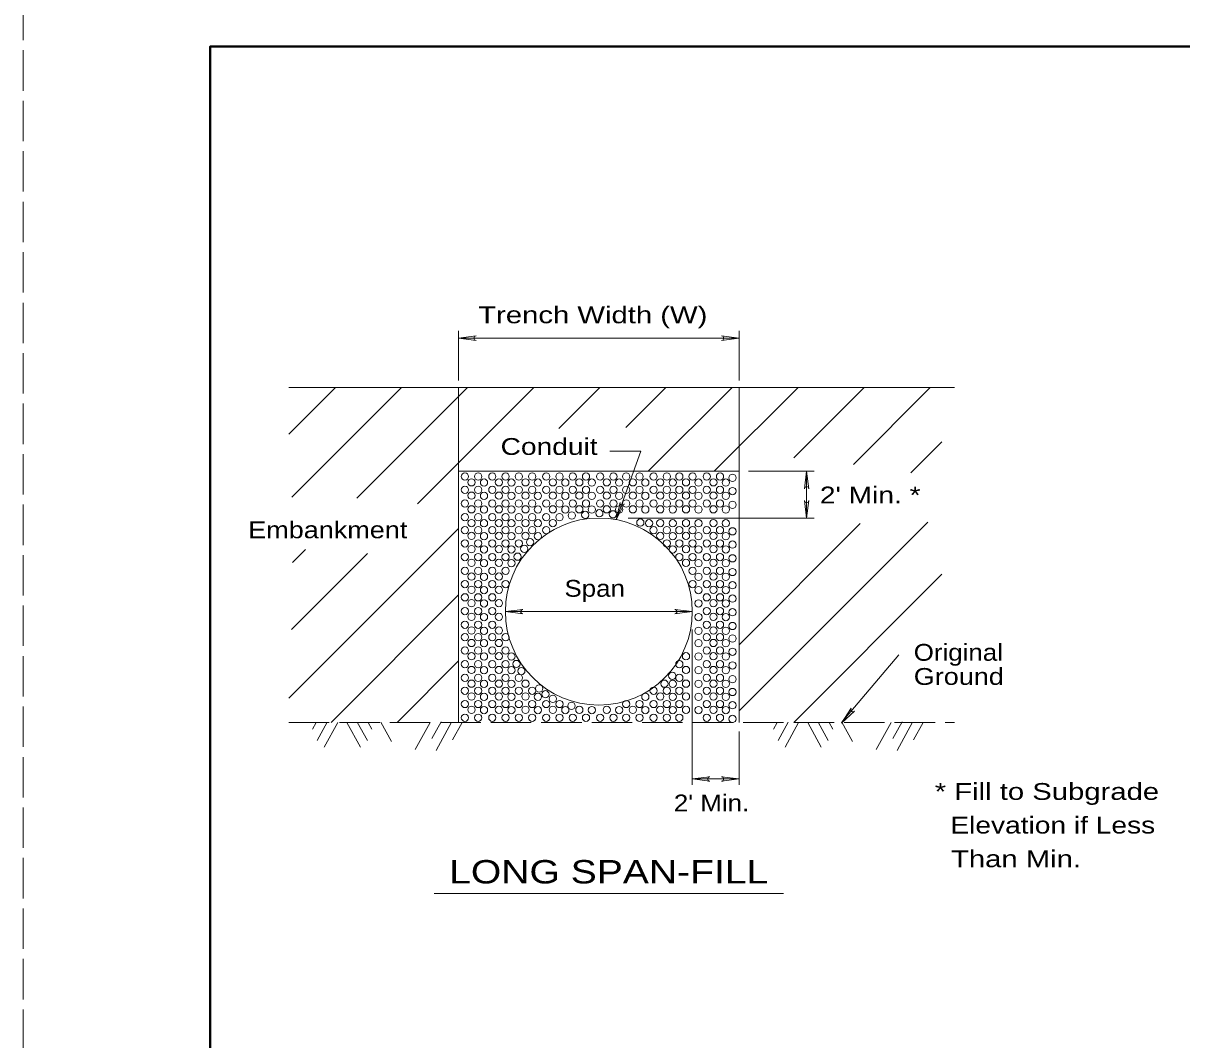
# Model space of a CAD drawing. Extents: x 750.7 to 784.7, y 834.8 to 878.8.
# Drawn here: x 750.65 to 763.05, y 845.66 to 856.53 of the extents above; entities that cross this region are included whole.
import ezdxf

# ---------------------------------------------------------------- set-up
doc = ezdxf.new("R2010")
doc.units = 0
doc.header["$LTSCALE"] = 0.072
doc.linetypes.add('LONG_DASHED', pattern=[7.5, 6, -1.5])
doc.layers.add('1', color=7, linetype='Continuous', lineweight=13)
doc.layers.add('47', color=7, linetype='Continuous', lineweight=13)

msp = doc.modelspace()

# ---------------------------------------------------------------- linework, layer by layer
at = {"layer": '1', "lineweight": 40}
msp.add_line((752.65083, 856.28433), (784.15083, 856.28433), dxfattribs=at)
at = {"layer": '1'}
for p, q in [((755.30908, 852.71117), (755.30908, 853.24292)), ((755.30908, 853.16492), (758.30908, 853.16492)), ((758.30908, 852.71117), (758.30908, 853.24292)), ((753.49175, 852.13867), (753.99142, 852.63842)), ((753.49367, 852.63842), (760.613, 852.63842)), ((753.52558, 851.46542), (754.6985, 852.63842)), ((754.22158, 851.45425), (755.40558, 852.63842)), ((754.86808, 851.39367), (756.11267, 852.63842)), ((755.30908, 852.63842), (755.30908, 849.05517)), ((756.3795, 852.19808), (756.81975, 852.63842)), ((757.097, 852.2085), (757.52683, 852.63842)), ((757.33717, 851.74158), (758.23392, 852.63842)), ((758.04417, 851.74158), (758.94092, 852.63842)), ((758.30908, 852.63842), (758.30908, 849.05517)), ((758.89425, 851.88467), (759.648, 852.63842)), ((759.53183, 851.81508), (760.35508, 852.63842)), ((760.148, 851.72417), (760.48017, 852.05642)), ((755.30908, 851.74158), (758.30908, 851.74158)), ((758.41008, 851.74158), (759.11142, 851.74158)), ((759.0315, 851.24025), (759.0315, 851.74158)), ((757.123, 851.24025), (759.11142, 851.24025)), ((758.30908, 849.17792), (760.32758, 851.19667)), ((758.30908, 849.88508), (759.60642, 851.18258)), ((753.49408, 849.31242), (755.30908, 851.12758)), ((753.52233, 850.04783), (754.33533, 850.86092)), ((753.53283, 850.7655), (753.67117, 850.90383)), ((758.8935, 849.05517), (760.477, 850.63883)), ((753.94392, 849.05517), (755.30908, 850.4205)), ((755.80908, 850.2405), (757.80908, 850.2405)), ((757.80908, 850.04683), (757.80908, 848.38733)), ((754.651, 849.05517), (755.30908, 849.71325)), ((759.40575, 849.05517), (760.01683, 849.77708)), ((755.12275, 849.0605), (755.02433, 848.88208)), ((760.053, 849.0605), (759.95458, 848.88208)), ((753.78683, 849.05517), (753.7475, 848.98383)), ((753.90342, 849.05658), (753.79558, 848.86108)), ((754.0155, 849.05267), (753.87058, 848.79008)), ((754.11342, 849.05267), (754.25833, 848.79008)), ((754.2255, 849.05658), (754.33333, 848.86108)), ((754.34208, 849.05517), (754.38142, 848.98383)), ((754.47842, 849.05567), (754.591, 848.85158)), ((755.00558, 849.05517), (754.845, 848.76417)), ((755.23475, 849.05658), (755.06858, 848.75542)), ((755.34683, 849.05267), (755.24508, 848.86825)), ((758.30908, 848.95567), (758.30908, 848.38733)), ((758.71708, 849.05517), (758.67775, 848.98383)), ((758.83367, 849.05658), (758.72583, 848.86108)), ((758.94575, 849.05267), (758.80083, 848.79008)), ((759.04367, 849.05267), (759.18858, 848.79008)), ((759.15575, 849.05658), (759.26358, 848.86108)), ((759.27233, 849.05517), (759.31167, 848.98383)), ((759.40867, 849.05567), (759.52125, 848.85158)), ((759.93583, 849.05517), (759.77525, 848.76417)), ((760.165, 849.05658), (759.99883, 848.75542)), ((760.27708, 849.05267), (760.17533, 848.86825)), ((757.80908, 848.4495), (758.30908, 848.4495)), ((755.04842, 847.22583), (758.78292, 847.22583))]:
    msp.add_line(p, q, dxfattribs=at)
at = {"layer": '1', "linetype": 'LONG_DASHED'}
msp.add_line((753.49367, 849.05517), (760.613, 849.05517), dxfattribs=at)
msp.add_lwpolyline([(750.65083, 834.78433), (784.65083, 834.78433), (784.65083, 856.78433), (750.65083, 856.78433)], close=True, dxfattribs=at)
at = {"layer": '1', "lineweight": 40}
for points in [[(784.15083, 835.28433), (752.65083, 835.28433), (752.65083, 856.28433), (784.15083, 856.28433)], [(784.15083, 835.28433), (752.65083, 835.28433), (752.65083, 856.28433)]]:
    msp.add_lwpolyline(points, dxfattribs=at)
at = {"layer": '1'}
msp.add_lwpolyline([(756.9255, 851.956), (757.26017, 851.956), (756.99517, 851.223)], dxfattribs=at)
for centre, radius in [((755.37663, 851.68461), 0.03892), ((755.44766, 851.62247), 0.03892), ((755.51866, 851.68464), 0.03892), ((755.66955, 851.68461), 0.03892), ((755.74058, 851.62247), 0.03892), ((755.81158, 851.68464), 0.03892), ((755.95363, 851.68461), 0.03892), ((756.02466, 851.62247), 0.03892), ((756.09566, 851.68464), 0.03892), ((756.24655, 851.68461), 0.03892), ((756.31758, 851.62247), 0.03892), ((756.38858, 851.68464), 0.03892), ((756.52963, 851.68461), 0.03892), ((756.60066, 851.62247), 0.03892), ((756.67166, 851.68464), 0.03892), ((756.82255, 851.68461), 0.03892), ((756.89358, 851.62247), 0.03892), ((756.96458, 851.68464), 0.03892), ((757.10221, 851.68461), 0.03892), ((757.17324, 851.62247), 0.03892), ((757.24424, 851.68464), 0.03892), ((757.39513, 851.68461), 0.03892), ((757.46616, 851.62247), 0.03892), ((757.53716, 851.68464), 0.03892), ((757.67038, 851.68461), 0.03892), ((757.74141, 851.62247), 0.03892), ((757.81241, 851.68464), 0.03892), ((757.9633, 851.68461), 0.03892), ((758.03433, 851.62247), 0.03892), ((758.10533, 851.68464), 0.03892), ((758.23849, 851.67131), 0.03892), ((755.37663, 851.54253), 0.03892), ((755.51866, 851.54256), 0.03892), ((755.58083, 851.62014), 0.03892), ((755.66955, 851.54253), 0.03892), ((755.81158, 851.54256), 0.03892), ((755.87374, 851.62014), 0.03892), ((755.95363, 851.54253), 0.03892), ((756.09566, 851.54256), 0.03892), ((756.15783, 851.62014), 0.03892), ((756.24655, 851.54253), 0.03892), ((756.38858, 851.54256), 0.03892), ((756.45074, 851.62014), 0.03892), ((756.52963, 851.54253), 0.03892), ((756.67166, 851.54256), 0.03892), ((756.73383, 851.62014), 0.03892), ((756.82255, 851.54253), 0.03892), ((756.96458, 851.54256), 0.03892), ((757.02674, 851.62014), 0.03892), ((757.10221, 851.54253), 0.03892), ((757.24424, 851.54256), 0.03892), ((757.30641, 851.62014), 0.03892), ((757.39513, 851.54253), 0.03892), ((757.53716, 851.54256), 0.03892), ((757.59933, 851.62014), 0.03892), ((757.67038, 851.54253), 0.03892), ((757.81241, 851.54256), 0.03892), ((757.87458, 851.62014), 0.03892), ((757.9633, 851.54253), 0.03892), ((758.10533, 851.54256), 0.03892), ((758.16749, 851.62014), 0.03892), ((758.23849, 851.52922), 0.03892), ((755.37663, 851.39603), 0.03892), ((755.44766, 851.48039), 0.03892), ((755.51866, 851.39606), 0.03892), ((755.58083, 851.47806), 0.03892), ((755.66955, 851.39603), 0.03892), ((755.74058, 851.48039), 0.03892), ((755.81158, 851.39606), 0.03892), ((755.87374, 851.47806), 0.03892), ((755.95363, 851.39603), 0.03892), ((756.02466, 851.48039), 0.03892), ((756.09566, 851.39606), 0.03892), ((756.15783, 851.47806), 0.03892), ((756.24655, 851.39603), 0.03892), ((756.31758, 851.48039), 0.03892), ((756.38858, 851.39606), 0.03892), ((756.45074, 851.47806), 0.03892), ((756.52963, 851.39603), 0.03892), ((756.60066, 851.48039), 0.03892), ((756.67166, 851.39606), 0.03892), ((756.73383, 851.47806), 0.03892), ((756.82255, 851.39603), 0.03892), ((756.89358, 851.48039), 0.03892), ((756.96458, 851.39606), 0.03892), ((757.02674, 851.47806), 0.03892), ((757.10221, 851.39603), 0.03892), ((757.17324, 851.48039), 0.03892), ((757.24424, 851.39606), 0.03892), ((757.30641, 851.47806), 0.03892), ((757.39513, 851.39603), 0.03892), ((757.46616, 851.48039), 0.03892), ((757.53716, 851.39606), 0.03892), ((757.59933, 851.47806), 0.03892), ((757.67038, 851.39603), 0.03892), ((757.74141, 851.48039), 0.03892), ((757.81241, 851.39606), 0.03892), ((757.87458, 851.47806), 0.03892), ((757.9633, 851.39603), 0.03892), ((758.03433, 851.48039), 0.03892), ((758.10533, 851.39606), 0.03892), ((758.16749, 851.47806), 0.03892), ((758.23849, 851.38272), 0.03892), ((755.44766, 851.33389), 0.03892), ((755.58083, 851.33156), 0.03892), ((755.74058, 851.33389), 0.03892), ((755.87374, 851.33156), 0.03892), ((756.02466, 851.33389), 0.03892), ((756.15783, 851.33156), 0.03892), ((756.31758, 851.33389), 0.03892), ((756.45074, 851.33156), 0.03892), ((756.52073, 851.26725), 0.03892), ((756.60066, 851.33389), 0.03892), ((756.66383, 851.27379), 0.03892), ((756.73383, 851.33156), 0.03892), ((756.81467, 851.29154), 0.03892), ((756.89358, 851.33389), 0.03892), ((756.96015, 851.28053), 0.03892), ((757.02674, 851.33156), 0.03892), ((757.17324, 851.33389), 0.03892), ((757.30641, 851.33156), 0.03892), ((757.46616, 851.33389), 0.03892), ((757.59933, 851.33156), 0.03892), ((757.74141, 851.33389), 0.03892), ((757.87458, 851.33156), 0.03892), ((758.03433, 851.33389), 0.03892), ((758.16749, 851.33156), 0.03892), ((755.37663, 851.24944), 0.03892), ((755.44766, 851.18731), 0.03892), ((755.51866, 851.24947), 0.03892), ((755.58083, 851.18497), 0.03892), ((755.66955, 851.24944), 0.03892), ((755.74058, 851.18731), 0.03892), ((755.81158, 851.24947), 0.03892), ((756.80908, 850.2405), 1), ((755.87374, 851.18497), 0.03892), ((755.95363, 851.24944), 0.03892), ((756.02466, 851.18731), 0.03892), ((756.09566, 851.24947), 0.03892), ((756.15783, 851.18497), 0.03892), ((756.24655, 851.24944), 0.03892), ((756.31758, 851.18731), 0.03892), ((756.38858, 851.24947), 0.03892), ((757.25314, 851.1917), 0.03892), ((757.34634, 851.18495), 0.03892), ((757.46616, 851.18731), 0.03892), ((757.59933, 851.18497), 0.03892), ((757.74141, 851.18731), 0.03892), ((757.87458, 851.18497), 0.03892), ((758.03433, 851.18731), 0.03892), ((758.16749, 851.18497), 0.03892), ((755.37663, 851.11178), 0.03892), ((755.44766, 851.04964), 0.03892), ((755.51866, 851.11181), 0.03892), ((755.58083, 851.04731), 0.03892), ((755.66955, 851.11178), 0.03892), ((755.74058, 851.04964), 0.03892), ((755.81158, 851.11181), 0.03892), ((755.87374, 851.04731), 0.03892), ((755.95363, 851.11178), 0.03892), ((756.02466, 851.04964), 0.03892), ((756.09566, 851.11181), 0.03892), ((756.15783, 851.04731), 0.03892), ((756.24655, 851.11178), 0.03892), ((757.39513, 851.11178), 0.03892), ((757.46616, 851.04964), 0.03892), ((757.53716, 851.11181), 0.03892), ((757.59933, 851.04731), 0.03892), ((757.67038, 851.11178), 0.03892), ((757.74141, 851.04964), 0.03892), ((757.81241, 851.11181), 0.03892), ((757.87458, 851.04731), 0.03892), ((757.9633, 851.11178), 0.03892), ((758.03433, 851.04964), 0.03892), ((758.10533, 851.11181), 0.03892), ((758.16749, 851.04731), 0.03892), ((758.23849, 851.09847), 0.03892), ((755.37663, 850.96969), 0.03892), ((755.44766, 850.90756), 0.03892), ((755.51866, 850.96972), 0.03892), ((755.58083, 850.90522), 0.03892), ((755.66955, 850.96969), 0.03892), ((755.74058, 850.90756), 0.03892), ((755.81158, 850.96972), 0.03892), ((755.87374, 850.90522), 0.03892), ((755.95363, 850.96969), 0.03892), ((756.01133, 850.91202), 0.03892), ((756.07342, 850.98305), 0.03892), ((757.53716, 850.96972), 0.03892), ((757.59933, 850.90522), 0.03892), ((757.67038, 850.96969), 0.03892), ((757.74141, 850.90756), 0.03892), ((757.81241, 850.96972), 0.03892), ((757.87458, 850.90522), 0.03892), ((757.9633, 850.96969), 0.03892), ((758.03433, 850.90756), 0.03892), ((758.10533, 850.96972), 0.03892), ((758.16749, 850.90522), 0.03892), ((758.23849, 850.95639), 0.03892), ((755.37663, 850.82319), 0.03892), ((755.44766, 850.76106), 0.03892), ((755.51866, 850.82322), 0.03892), ((755.58083, 850.75872), 0.03892), ((755.66955, 850.82319), 0.03892), ((755.74058, 850.76106), 0.03892), ((755.81158, 850.82322), 0.03892), ((755.87374, 850.75872), 0.03892), ((755.94034, 850.82761), 0.03892), ((757.67038, 850.82319), 0.03892), ((757.74141, 850.76106), 0.03892), ((757.81241, 850.82322), 0.03892), ((757.87458, 850.75872), 0.03892), ((757.9633, 850.82319), 0.03892), ((758.03433, 850.76106), 0.03892), ((758.10533, 850.82322), 0.03892), ((758.16749, 850.75872), 0.03892), ((758.23849, 850.80989), 0.03892), ((755.37663, 850.67661), 0.03892), ((755.51866, 850.67664), 0.03892), ((755.66955, 850.67661), 0.03892), ((755.81158, 850.67664), 0.03892), ((757.81241, 850.67664), 0.03892), ((757.9633, 850.67661), 0.03892), ((758.10533, 850.67664), 0.03892), ((758.23849, 850.66331), 0.03892), ((755.37663, 850.53461), 0.03892), ((755.44766, 850.61447), 0.03892), ((755.51866, 850.53464), 0.03892), ((755.58083, 850.61214), 0.03892), ((755.66955, 850.53461), 0.03892), ((755.74058, 850.61447), 0.03892), ((755.81158, 850.53464), 0.03892), ((757.81241, 850.53464), 0.03892), ((757.87458, 850.61214), 0.03892), ((757.9633, 850.53461), 0.03892), ((758.03433, 850.61447), 0.03892), ((758.10533, 850.53464), 0.03892), ((758.16749, 850.61214), 0.03892), ((758.23849, 850.52131), 0.03892), ((755.37663, 850.39253), 0.03892), ((755.44766, 850.47247), 0.03892), ((755.51866, 850.39256), 0.03892), ((755.58083, 850.47014), 0.03892), ((755.66955, 850.39253), 0.03892), ((755.74058, 850.47247), 0.03892), ((757.87458, 850.47014), 0.03892), ((757.9633, 850.39253), 0.03892), ((758.03433, 850.47247), 0.03892), ((758.10533, 850.39256), 0.03892), ((758.16749, 850.47014), 0.03892), ((755.44766, 850.33039), 0.03892), ((755.58083, 850.32806), 0.03892), ((755.74058, 850.33039), 0.03892), ((757.87458, 850.32806), 0.03892), ((758.03433, 850.33039), 0.03892), ((758.16749, 850.32806), 0.03892), ((758.23849, 850.37922), 0.03892), ((755.37663, 850.24603), 0.03892), ((755.44766, 850.18389), 0.03892), ((755.51866, 850.24606), 0.03892), ((755.58083, 850.18156), 0.03892), ((755.66955, 850.24603), 0.03892), ((755.74058, 850.18389), 0.03892), ((757.87458, 850.18156), 0.03892), ((757.9633, 850.24603), 0.03892), ((758.03433, 850.18389), 0.03892), ((758.10533, 850.24606), 0.03892), ((758.16749, 850.18156), 0.03892), ((758.23849, 850.23272), 0.03892), ((755.37663, 850.09944), 0.03892), ((755.44766, 850.03731), 0.03892), ((755.51866, 850.09947), 0.03892), ((755.58083, 850.03497), 0.03892), ((755.66955, 850.09944), 0.03892), ((755.74058, 850.03731), 0.03892), ((757.87458, 850.03497), 0.03892), ((757.9633, 850.09944), 0.03892), ((758.03433, 850.03731), 0.03892), ((758.10533, 850.09947), 0.03892), ((758.16749, 850.03497), 0.03892), ((758.23849, 850.08614), 0.03892), ((755.37663, 849.96628), 0.03892), ((755.44766, 849.90414), 0.03892), ((755.51866, 849.96631), 0.03892), ((755.58083, 849.90181), 0.03892), ((755.66955, 849.96628), 0.03892), ((755.74058, 849.90414), 0.03892), ((755.81158, 849.96631), 0.03892), ((757.87458, 849.90181), 0.03892), ((757.9633, 849.96628), 0.03892), ((758.03433, 849.90414), 0.03892), ((758.10533, 849.96631), 0.03892), ((758.16749, 849.90181), 0.03892), ((758.23849, 849.95297), 0.03892), ((755.37663, 849.82419), 0.03892), ((755.51866, 849.82422), 0.03892), ((755.66955, 849.82419), 0.03892), ((755.81158, 849.82422), 0.03892), ((757.9633, 849.82419), 0.03892), ((758.10533, 849.82422), 0.03892), ((758.23849, 849.81089), 0.03892), ((755.37663, 849.67769), 0.03892), ((755.44766, 849.76206), 0.03892), ((755.51866, 849.67772), 0.03892), ((755.58083, 849.75972), 0.03892), ((755.66955, 849.67769), 0.03892), ((755.74058, 849.76206), 0.03892), ((755.81158, 849.67772), 0.03892), ((755.87374, 849.75972), 0.03892), ((755.927, 849.67979), 0.03892), ((757.67038, 849.67769), 0.03892), ((757.74141, 849.76206), 0.03892), ((757.87458, 849.75972), 0.03892), ((757.9633, 849.67769), 0.03892), ((758.03433, 849.76206), 0.03892), ((758.10533, 849.67772), 0.03892), ((758.16749, 849.75972), 0.03892), ((758.23849, 849.66439), 0.03892), ((755.37663, 849.53111), 0.03892), ((755.44766, 849.61556), 0.03892), ((755.51866, 849.53114), 0.03892), ((755.58083, 849.61322), 0.03892), ((755.66955, 849.53111), 0.03892), ((755.74058, 849.61556), 0.03892), ((755.81158, 849.53114), 0.03892), ((755.87374, 849.61322), 0.03892), ((755.95363, 849.53111), 0.03892), ((755.98025, 849.60429), 0.03892), ((757.59485, 849.55334), 0.03892), ((757.67038, 849.53111), 0.03892), ((757.74141, 849.61556), 0.03892), ((757.87458, 849.61322), 0.03892), ((757.9633, 849.53111), 0.03892), ((758.03433, 849.61556), 0.03892), ((758.10533, 849.53114), 0.03892), ((758.16749, 849.61322), 0.03892), ((758.23849, 849.51781), 0.03892), ((755.37663, 849.39344), 0.03892), ((755.44766, 849.46897), 0.03892), ((755.51866, 849.39347), 0.03892), ((755.58083, 849.46664), 0.03892), ((755.66955, 849.39344), 0.03892), ((755.74058, 849.46897), 0.03892), ((755.81158, 849.39347), 0.03892), ((755.87374, 849.46664), 0.03892), ((755.95363, 849.39344), 0.03892), ((756.02466, 849.46897), 0.03892), ((756.09566, 849.39347), 0.03892), ((756.17108, 849.41787), 0.03892), ((757.39513, 849.39344), 0.03892), ((757.51051, 849.46892), 0.03892), ((757.53716, 849.39347), 0.03892), ((757.59933, 849.46664), 0.03892), ((757.67038, 849.39344), 0.03892), ((757.74141, 849.46897), 0.03892), ((757.87458, 849.46664), 0.03892), ((757.9633, 849.39344), 0.03892), ((758.03433, 849.46897), 0.03892), ((758.10533, 849.39347), 0.03892), ((758.16749, 849.46664), 0.03892), ((755.44766, 849.33131), 0.03892), ((755.58083, 849.32897), 0.03892), ((755.74058, 849.33131), 0.03892), ((755.87374, 849.32897), 0.03892), ((756.02466, 849.33131), 0.03892), ((756.15783, 849.32897), 0.03892), ((756.23767, 849.35571), 0.03892), ((756.31758, 849.30679), 0.03892), ((757.30641, 849.32897), 0.03892), ((757.46616, 849.33131), 0.03892), ((757.59933, 849.32897), 0.03892), ((757.74141, 849.33131), 0.03892), ((757.87458, 849.32897), 0.03892), ((758.03433, 849.33131), 0.03892), ((758.16749, 849.32897), 0.03892), ((758.23849, 849.38014), 0.03892), ((755.37663, 849.25136), 0.03892), ((755.44766, 849.18922), 0.03892), ((755.51866, 849.25139), 0.03892), ((755.58083, 849.18689), 0.03892), ((755.66955, 849.25136), 0.03892), ((755.74058, 849.18922), 0.03892), ((755.81158, 849.25139), 0.03892), ((755.87374, 849.18689), 0.03892), ((755.95363, 849.25136), 0.03892), ((756.02466, 849.18922), 0.03892), ((756.09566, 849.25139), 0.03892), ((756.15783, 849.18689), 0.03892), ((756.24655, 849.25136), 0.03892), ((756.31758, 849.18922), 0.03892), ((756.38858, 849.25139), 0.03892), ((756.45074, 849.18689), 0.03892), ((756.51733, 849.23137), 0.03892), ((756.60066, 849.18922), 0.03892), ((756.73383, 849.18689), 0.03892), ((756.89358, 849.18922), 0.03892), ((757.02674, 849.18689), 0.03892), ((757.10221, 849.25136), 0.03892), ((757.17324, 849.18922), 0.03892), ((757.24424, 849.25139), 0.03892), ((757.30641, 849.18689), 0.03892), ((757.39513, 849.25136), 0.03892), ((757.46616, 849.18922), 0.03892), ((757.53716, 849.25139), 0.03892), ((757.59933, 849.18689), 0.03892), ((757.67038, 849.25136), 0.03892), ((757.74141, 849.18922), 0.03892), ((757.87458, 849.18689), 0.03892), ((757.9633, 849.25136), 0.03892), ((758.03433, 849.18922), 0.03892), ((758.10533, 849.25139), 0.03892), ((758.16749, 849.18689), 0.03892), ((758.23849, 849.23806), 0.03892), ((755.37663, 849.10486), 0.03892), ((755.51866, 849.10489), 0.03892), ((755.66955, 849.10486), 0.03892), ((755.81158, 849.10489), 0.03892), ((755.95363, 849.10486), 0.03892), ((756.09566, 849.10489), 0.03892), ((756.24655, 849.10486), 0.03892), ((756.38858, 849.10489), 0.03892), ((756.52963, 849.10486), 0.03892), ((756.67166, 849.10489), 0.03892), ((756.82255, 849.10486), 0.03892), ((756.96458, 849.10489), 0.03892), ((757.10221, 849.10486), 0.03892), ((757.24424, 849.10489), 0.03892), ((757.39513, 849.10486), 0.03892), ((757.53716, 849.10489), 0.03892), ((757.67038, 849.10486), 0.03892), ((757.9633, 849.10486), 0.03892), ((758.10533, 849.10489), 0.03892), ((758.23849, 849.09156), 0.03892)]:
    msp.add_circle(centre, radius, dxfattribs=at)
at = {"layer": '47'}
for points in [[(755.49658, 853.18833), (755.30908, 853.16492), (755.49658, 853.1415)], [(758.12158, 853.1415), (758.30908, 853.16492), (758.12158, 853.18833)], [(759.00808, 851.55408), (759.0315, 851.74158), (759.05492, 851.55408)], [(759.05492, 851.42775), (759.0315, 851.24025), (759.00808, 851.42775)], [(757.08092, 851.39133), (756.99517, 851.223), (757.03692, 851.40733)], [(755.99658, 850.21708), (755.80908, 850.2405), (755.99658, 850.26392)], [(757.62158, 850.26392), (757.80908, 850.2405), (757.62158, 850.21708)], [(759.54525, 849.17608), (759.40625, 849.04808), (759.5095, 849.20633)], [(757.99658, 848.42608), (757.80908, 848.4495), (757.99658, 848.47292)], [(758.12158, 848.47292), (758.30908, 848.4495), (758.12158, 848.42608)]]:
    msp.add_lwpolyline(points, dxfattribs=at)
for centre, start, end in [((755.49659, 853.16493), 90, 270), ((758.12158, 853.16494), 270, 90), ((759.03151, 851.55408), 0, 180), ((759.03149, 851.42776), 180, 0), ((757.05891, 851.39934), 160.12536, 340.12536), ((755.99659, 850.24051), 90, 270), ((757.62158, 850.24049), 270, 90), ((759.52739, 849.1912), 139.75297, 319.75297), ((757.99659, 848.44951), 90, 270), ((758.12158, 848.44949), 270, 90)]:
    msp.add_arc(centre, 0.02342, start, end, dxfattribs=at)

# ---------------------------------------------------------------- texts
at = {"layer": '1'}
for s, height, width, p in [('Trench Width (W)', 0.18, 1.3, (755.51892, 853.32425)), ('Conduit', 0.18, 1.25, (755.75858, 851.91617)), ("2' Min. *", 0.18, 1.25, (759.17358, 851.39692)), ('Embankment', 0.18, 1.2, (753.0585, 851.02458)), ('Span', 0.18, 1.15, (756.44142, 850.39867)), ('Original', 0.18, 1.15, (760.17808, 849.71408)), ('Ground', 0.18, 1.2, (760.17808, 849.45608)), ('* Fill to Subgrade', 0.18, 1.3, (760.4025, 848.22592)), ("2' Min.", 0.18, 1.15, (757.61117, 848.10317)), ('  Elevation if Less', 0.18, 1.25, (760.4025, 847.86592)), ('  Than Min.', 0.18, 1.3, (760.4025, 847.50592)), ('LONG SPAN-FILL', 0.25, 1.25, (755.20783, 847.33217))]:
    msp.add_text(s, height=height, dxfattribs=dict(at, width=width)).set_placement(p)

doc.saveas('drawing.dxf')
